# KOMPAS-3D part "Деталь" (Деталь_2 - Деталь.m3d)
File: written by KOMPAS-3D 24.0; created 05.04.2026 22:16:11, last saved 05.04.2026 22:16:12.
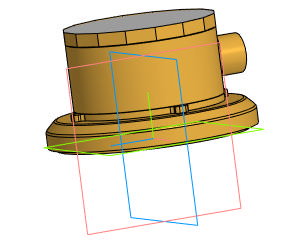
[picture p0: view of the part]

Document properties: Автор: tyuri; Полное имя файла: D:\Аутсорс\Клапан балансировочный автоматический DN.ru VBA0000E-T Ду15 Ру16\DN15\Исходные файлы\Деталь_2 - Деталь.m3d

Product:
- Body: Твердое тело1  | qty 1
- Part/product: Деталь
    additional columns: Типовые

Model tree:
1. Твердое тело1  (labels: Твердое тело1)
2. Эскиз:1  (labels: Грань.Твердое тело1)
3. Элемент выдавливания:1
     Расстояние 2 = 39.8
